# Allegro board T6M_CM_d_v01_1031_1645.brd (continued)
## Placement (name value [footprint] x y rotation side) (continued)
R199  0  [R0402]  58.61 102.4 90 top
R200  8.06K  [R0402]  64.13 81.48 180 bottom
R202  100  [R0402]  82.38 29.39 270 bottom
R203  100  [R0402]  80.35 29.39 90 bottom
R204  0  [R0402]  77.23 28.09 180 bottom
R205  0  [R0402]  111.55 17.69 0 top
R206  0  [R0402]  107.77 29.93 180 bottom
R207  0  [R0402]  101.99 17.6 0 top
R208  0  [R0402]  97.73 29.79 0 bottom
R209  0  [R0402]  68.72 21.5 180 bottom
R210  0  [R0402]  65.23 29.2 180 bottom
R211  0  [R0402]  60.69 28.7 0 bottom
R212  0  [R0402]  50.38 19.02 180 top
R213  12.1K  [R0402]  20.37 7.73 0 top
R214  12.1K  [R0402]  20.37 6.71 180 top
R215  100  [R0402]  24.62 11.61 90 top
R216  2.2  [R0402]  22.6 11.61 270 top
R217  0  [R0402]  46.35 19.45 0 top
R218  100  [R0402]  23.61 11.61 270 top
R219  1K  [R0402]  116.44 66.16 0 bottom
R220  1K  [R0402]  116.44 65.15 180 bottom
R221  0  [R0402]  126.78 65.4 0 top
R222  0  [R0402]  116.44 64.13 0 bottom
R223  1K  [R0402]  128.56 63.42 180 top
R224  0  [R0402]  122.72 67.03 270 bottom
R225  0  [R0402]  126.08 60.24 180 top
R226  1K  [R0402]  116.44 69.27 180 bottom
R227  0  [R0402]  116.44 68.24 0 bottom
R228  150  [R0402]  126.08 62.27 180 top
R229  51  [R0402]  126.08 61.26 0 top
R231  0  [R0402]  147.83 154.82 90 top
R232  0  [R0402]  156.95 141.2 0 top
R233  0  [R0402]  156.97 142.2 0 top
R234  0  [R0402]  146.84 154.82 270 top
R253  100K  [R0402]  81.43 121.04 270 bottom
R254  0  [R0402]  82.72 121.06 270 bottom
R255  0  [R0402]  80.39 121.04 270 top
R256  10K  [R0402]  87.45 129.39 270 bottom
R257  274  [R0402]  69.49 131.03 180 bottom
R258  100K  [R0402]  88.6 129.39 90 bottom
R259  4.7K  [R0402]  54.36 123.47 90 top
R260  240  [R0402]  57.75 133.13 180 bottom
R261  1K  [R0402]  49 133.45 270 bottom
R262  1K  [R0402]  49.68 138.39 180 bottom
R263  0  [R0402]  156.95 137.37 180 top
R264  0  [R0402]  181.68 37.95 0 top
R265  0  [R0402]  181.68 36.94 0 top
R266  0  [R0402]  181.76 41.68 0 top
R267  0  [R0402]  181.76 40.66 0 top
R268  0  [R0402]  181.68 58 0 top
R269  0  [R0402]  181.68 56.98 0 top
R270  0  [R0402]  181.82 61.68 0 top
R271  0  [R0402]  181.82 60.67 0 top
R272  0  [R0402]  83.75 121.06 270 bottom
R273  0  [R0402]  168.07 105.98 270 top
R274  0  [R0402]  169.1 105.98 270 top
R275  5.1K  [R0402]  159.47 144.08 0 top
R276  5.1K  [R0402]  156.95 144.2 0 top
R277  5.1K  [R0402]  156.95 145.22 0 top
R278  5.1K  [R0402]  156.82 150.2 0 top
R279  5.1K  [R0402]  150.95 154.79 90 top
R280  5.1K  [R0402]  139.55 133.18 270 top
R281  5.1K  [R0402]  135.33 137.04 180 top
R283  5.1K  [R0402]  138.58 153.68 90 top
R284  5.1K  [R0402]  160.23 138.49 0 top
R285  5.1K  [R0402]  156.8 149.21 0 top
R286  5.1K  [R0402]  156.95 140.21 0 top
R287  5.1K  [R0402]  149.81 154.79 90 top
R288  5.1K  [R0402]  156.95 138.54 0 top
R289  5.1K  [R0402]  154.94 133.18 0 top
R290  150  [R0402]  70.91 146.42 270 bottom
R291  150  [R0402]  72.03 146.42 270 bottom
R292  150  [R0402]  73.12 146.42 270 bottom
R293  10K  [R0402]  86.94 148.48 270 bottom
R294  8.2K  [R0402]  69.38 126.52 0 bottom
R295  5.1K  [R0402]  137.57 153.68 90 top
R296  5.1K  [R0402]  139.6 153.68 90 top
R297  5.1K  [R0402]  142.51 154.7 180 top
R298  47K  [R0402]  83.74 148.48 90 top
R299  5.1K  [R0402]  145.8 154.84 270 top
R300  47K  [R0402]  81.58 148.48 90 top
R301  5.1K  [R0402]  159.96 150.24 90 top
R302  47K  [R0402]  80.51 148.48 90 top
R303  5.1K  [R0402]  158.95 150.24 90 top
R304  47K  [R0402]  82.67 148.48 90 top
R305  5.1K  [R0402]  154.94 135.19 180 top
R306  5.1K  [R0402]  156.77 147.2 0 top
R307  5.1K  [R0402]  156.8 148.22 0 top
R308  5.1K  [R0402]  156.77 146.21 0 top
R309  5.1K  [R0402]  160.09 141.03 180 top
R310  5.1K  [R0402]  160.07 142.1 180 top
R311  4.7K  [R0402]  63.34 117.87 270 top
R312  22  [R0402]  67.82 121.34 270 top
R313  49.9K  [R0402]  77.34 148.48 90 top
R314  0  [R0603]  71.96 149.69 0 top
R315  2.74K  [R0603]  68.76 148.29 180 top
R316  4.7K  [R0402]  74.54 121.06 270 bottom
R317  4.7K  [R0402]  72.39 118.91 90 top
R318  4.7K  [R0402]  72.39 121.04 270 top
R319  4.7K  [R0402]  73.5 118.91 90 bottom
R320  4.7K  [R0402]  75.86 118.78 90 bottom
R321  4.7K  [R0402]  75.86 121.04 270 bottom
R322  4.7K  [R0402]  73.5 118.91 90 top
R323  4.7K  [R0402]  73.48 121.04 270 top
R324  4.7K  [R0402]  79.32 118.76 90 bottom
R325  4.7K  [R0402]  78.23 121.04 270 bottom
R326  4.7K  [R0402]  75.86 118.78 90 top
R327  4.7K  [R0402]  75.86 121.04 270 top
R328  4.7K  [R0402]  77.75 129.79 90 bottom
R329  4.7K  [R0402]  80.41 118.76 90 bottom
R330  4.7K  [R0402]  80.39 121.04 270 bottom
R331  4.7K  [R0402]  76.93 121.04 270 top
R332  4.7K  [R0402]  71.8 119.05 270 bottom
R333  4.7K  [R0402]  78.23 118.76 90 bottom
R334  4.7K  [R0402]  76.93 118.76 90 bottom
R335  4.7K  [R0402]  79.32 121.04 270 bottom
R336  4.7K  [R0402]  74.54 121.04 270 top
R337  4.7K  [R0402]  76.93 121.04 270 bottom
R338  4.7K  [R0402]  76.93 118.76 90 top
R339  4.7K  [R0402]  81.5 118.76 90 bottom
R340  4.7K  [R0402]  71.29 121.04 270 top
R341  4.7K  [R0402]  71.29 118.91 90 top
R342  4.7K  [R0402]  73.48 121.04 270 bottom
R343  4.7K  [R0402]  70.01 118.96 270 top
R344  4.7K  [R0402]  68.92 118.97 270 top
R345  4.7K  [R0402]  78.23 118.76 90 top
R346  4.7K  [R0402]  78.23 121.04 270 top
R471  0  [R0402]  23.15 3.71 180 top
R472  0  [R0402]  23.15 4.72 180 top
R497  1K  [R0402]  68.1 96.71 90 top
R501  330  [R0402]  150.91 69.66 180 top
R502  4.7K  [R0402]  161.31 57.25 270 top
R503  10K  [R0402]  164.58 60.02 0 top
R504  6.04K  [R0402]  164.61 70.2 180 top
R505  10K  [R0402]  164.61 69.06 0 top
R506  33  [R0402]  151.39 76.49 180 top
R507  33  [R0402]  151.39 75.39 180 top
R508  33  [R0402]  151.47 74.3 180 top
R509  4.7K  [R0402]  149.63 61.72 180 top
R510  4.7K  [R0402]  149.63 62.74 180 top
R511  4.7K  [R0402]  149.63 60.7 180 top
R512  4.7K  [R0402]  149.63 59.69 180 top
R513  0  [R0402]  155.38 72.31 270 top
R514  4.7K  [R0402]  160.29 57.25 270 top
R515  4.7K  [R0402]  159.28 57.25 270 top
R516  4.7K  [R0402]  143.01 60.93 90 top
R517  4.7K  [R0402]  162.33 57.25 270 top
R518  4.7K  [R0402]  163.34 57.25 270 top
R519  33  [R0402]  144.03 60.93 90 top
R520  0  [R0402]  167.48 103.99 270 top
R521  0  [R0402]  135.62 56.83 0 top
R522  33  [R0402]  175.92 93.84 270 top
R523  33  [R0402]  174.91 93.84 270 top
R524  33  [R0402]  176.94 93.84 270 top
R525  10K  [R0402]  171.58 106.37 180 top
R526  1.6K  [R0402]  183.91 93.88 180 top
R527  10K  [R0402]  172.42 97.32 180 top
R528  10K  [R0402]  165.53 87.17 270 top
R529  10K  [R0402]  175.75 88.85 0 top
R530  33  [R0402]  165.47 89.2 270 top
R531  47K  [R0402]  165.57 91.33 270 top
R532  10K  [R0402]  178.13 93.85 90 top
R533  10K  [R0402]  172.04 98.34 180 top
R534  10K  [R0402]  168.48 103.99 270 top
R536  4.7K  [R0402]  59.63 163.9 90 top
R537  1K  [R0402]  60.78 163.9 90 top
R538  4.7K  [R0402]  63.06 163.9 90 top
R539  4.7K  [R0402]  64.21 163.9 90 top
R540  4.7K  [R0402]  61.92 163.9 90 top
R541  4.7K  [R0402]  59.63 166.44 90 top
R542  4.7K  [R0402]  64.26 147.55 0 top
R543  0  [R0402]  64.26 148.56 180 top
R544  10K  [R0402]  57.57 145.83 270 top
R545  22.1  [R0402]  64.26 145.51 180 top
R546  10K  [R0402]  56.55 145.83 270 top
R547  0  [R0402]  70.25 161.93 90 top
R548  10K  [R0402]  54.36 145.8 270 top
R549  0  [R0402]  64.26 146.53 180 top
R550  10K  [R0402]  53.35 145.8 270 top
R551  1K  [R0402]  49.96 145.57 180 bottom
R552  1K  [R0402]  49.96 146.58 180 bottom
R553  10K  [R0402]  69.23 161.93 270 top
R554  10K  [R0402]  49.96 147.58 180 bottom
R555  10K  [R0402]  74.97 151.48 180 top
R556  10K  [R0402]  55.45 145.83 270 top
R557  10K  [R0402]  52.27 145.83 270 top
R558  1.02K  [R0402]  65.59 159 0 top
R559  4.99K  [R0402]  52.16 162.19 90 top
R560  0  [R0402]  64.26 149.58 0 top
R561  0  [R0402]  63.06 166.44 90 top
R562  0  [R0402]  61.92 166.44 90 top
R563  0  [R0402]  64.21 166.44 90 top
R564  4.99K  [R0603]  36.07 149.12 180 top
R565  0  [R1206]  41.59 147.96 90 top
R566  4.7K  [R0402]  165.56 142.89 270 top
R567  4.7K  [R0402]  170 142.94 270 top
R568  1K  [R0402]  167.72 142.94 270 top
R569  4.7K  [R0402]  163.53 142.89 270 top
R570  4.7K  [R0402]  161.5 142.89 270 top
R571  4.7K  [R0402]  168.86 142.94 270 top
R572  4.7K  [R0402]  169.34 161.2 90 top
R573  0  [R0402]  166.58 167.79 180 top
R574  10K  [R0402]  172.09 161.37 90 top
R575  22.1  [R0402]  177.84 165.12 0 top
R576  10K  [R0402]  173.1 161.37 90 top
R577  0  [R0402]  177.84 163.85 0 top
R578  10K  [R0402]  175.29 161.4 90 top
R579  0  [R0402]  166.58 166.52 180 top
R580  10K  [R0402]  176.3 161.4 90 top
R581  1K  [R0402]  181.17 154.8 0 bottom
R582  1K  [R0402]  180.54 156.83 0 top
R583  10K  [R0402]  177.84 166.39 180 top
R584  10K  [R0402]  178.45 161.4 90 top
R585  10K  [R0402]  166.58 165.25 0 top
R586  10K  [R0402]  174.2 161.37 90 top
R587  10K  [R0402]  177.38 161.37 90 top
R588  1.02K  [R0402]  164.7 149.07 180 top
R589  4.99K  [R0402]  177.5 145.83 270 top
R590  0  [R0402]  167.29 161.21 90 top
R591  0  [R0402]  164.54 142.89 270 top
R592  0  [R0402]  166.58 142.89 270 top
R593  0  [R0402]  162.51 142.89 270 top
R594  4.99K  [R0603]  194.46 145.2 270 top
R595  0  [R1206]  194.49 149.21 270 top
R596  1K  [R0402]  65.59 157.98 0 top
R597  1K  [R0402]  164.69 150.14 180 top
R614  10K  [R0402]  147.29 51.44 90 top
R615  10K  [R0402]  145.26 51.44 90 top
R616  10K  [R0402]  140.06 51.75 90 top
R617  10K  [R0402]  135.04 50.04 90 top
R618  0  [R0402]  131.17 39.94 180 top
R619  1K  [R0402]  125.98 46.85 0 top
R620  10K  [R0402]  138.07 40.07 0 bottom
R621  0  [R0402]  136.79 50.08 90 top
R622  0  [R0402]  88.78 164.13 180 bottom
R623  0  [R0402]  135.74 166.52 0 top
R624  1K  [R0402]  134.85 26.57 90 top
R625  0  [R0402]  131.16 41.53 180 top
R626  10K  [R0402]  161.43 45.71 0 top
R627  0  [R0402]  179.66 131.77 90 top
R628  10_4  [R0402]  137.58 32.68 0 bottom
R629  0  [R0805]  157.11 51.67 270 top
R630  0  [R0805]  159.14 51.67 270 top
R631  4.7K  [R0402]  32.45 62.2 90 top
R632  4.7K  [R0402]  38.01 44.1 270 top
R633  4.7K  [R0402]  32.45 64.07 270 top
R634  4.7K  [R0402]  30.25 45.51 270 top
R635  4.7K  [R0402]  27.32 62.09 270 top
R636  0  [R0402]  27.32 63.89 270 top
R637  33  [R0402]  27.28 60.31 90 top
R638  33  [R0402]  28.52 52.33 270 top
R639  33  [R0402]  28.59 46.32 270 top
R640  150  [R0402]  31.42 43.84 180 top
R641  150  [R0402]  30.08 47.99 180 top
R642  150  [R0402]  30.26 56 270 top
R643  0  [R0402]  135.28 161.24 180 top
R644  0  [R0402]  132.65 153.9 270 top
R645  0  [R0402]  132.29 159.5 270 top
R646  0  [R0402]  120.42 162.73 180 top
R647  0  [R0402]  148.48 158.55 0 top
R648  0  [R0402]  140.55 161.24 180 top
R649  4.7K  [R0402]  161.54 32.57 180 top
R650  4.7K  [R0402]  161.54 33.59 180 top
R651  4.7K  [R0402]  24.98 16.26 270 top
R652  4.7K  [R0402]  23.97 16.26 270 top
R653  4.7K  [R0402]  145.3 60.93 270 top
R654  1K  [R0402]  23.92 29.78 90 top
R655  10K  [R0402]  110.19 162.23 270 top
R656  1K  [R0402]  173.23 33.59 0 top
R657  10K  [R0402]  120.42 153.55 0 top
R658  0  [R0402]  36.86 57.36 180 top
R659  33  [R0402]  30.26 54.25 90 top
R660  0  [R0402]  180.69 131.72 90 top
R661  0  [R0402]  181.85 131.72 90 top
R662  0  [R0402]  81.79 166.75 180 top
R663  2.7K  [R0402]  123.9 172.63 180 top
R664  2.7K  [R0402]  123.9 171.61 180 top
R665  10K  [R0402]  137.05 161.19 0 top
R666  4.7K  [R0402]  123.9 170.59 180 top
R667  10K  [R0402]  123.9 169.58 180 top
R668  4.7K  [R0402]  131.27 160.4 90 top
R669  10K  [R0402]  140.55 162.25 0 top
R670  33  [R0402]  68.23 144.81 0 bottom
R671  4.7K  [R0402]  148.48 157.54 0 top
R672  10K  [R0402]  135.74 169.57 0 top
R673  4.7K  [R0402]  123.9 166.52 0 top
R674  10K  [R0402]  135.74 170.59 0 top
R675  33  [R0402]  68.23 145.85 0 bottom
R676  0  [R0402]  81.79 165.66 180 top
R677  10K  [R0402]  123.9 165.51 180 top
R678  0  [R0402]  81.79 164.62 180 top
R679  0  [R0402]  138.68 165.26 180 top
R680  10K  [R0402]  135.74 164.49 180 top
R681  0  [R0402]  124.1 164.31 0 top
R682  100  [R0402]  135.74 171.6 0 top
R683  0  [R0402]  124.1 163.28 0 top
R684  0  [R0402]  138.68 164.23 180 top
R685  4.7K  [R0402]  90.86 169.46 180 bottom
R686  4.7K  [R0402]  73.73 178.6 0 bottom
R687  100  [R0402]  102.85 169.96 180 bottom
R688  100  [R0402]  60.39 178.29 0 bottom
R689  10K  [R0402]  90.86 170.47 0 bottom
R690  10K  [R0402]  90.86 171.49 0 bottom
R691  10K  [R0402]  90.86 172.51 0 bottom
R692  10K  [R0402]  90.86 173.52 0 bottom
R693  10K  [R0402]  90.86 174.54 0 bottom
R694  10K  [R0402]  90.86 175.55 0 bottom
R695  10K  [R0402]  90.86 176.57 0 bottom
R696  10K  [R0402]  90.86 177.59 0 bottom
R697  10K  [R0402]  102.85 178.09 180 bottom
R698  10K  [R0402]  102.85 177.07 180 bottom
R699  10K  [R0402]  102.85 176.05 180 bottom
R700  10K  [R0402]  102.85 175.04 180 bottom
R701  4.7K  [R0402]  106.48 172.12 180 bottom
R702  4.7K  [R0402]  122.48 172.51 180 bottom
R703  10K  [R0402]  102.85 174.02 180 bottom
R704  4.7K  [R0402]  118.82 174.16 0 bottom
R705  10K  [R0402]  102.85 173.01 180 bottom
R706  4.7K  [R0402]  135.74 173.39 0 bottom
R707  10K  [R0402]  102.85 171.99 180 bottom
R708  4.7K  [R0402]  106.48 174.16 180 bottom
R709  10K  [R0402]  102.85 170.97 180 bottom
R710  10K  [R0402]  122.48 174.54 0 bottom
R711  10K  [R0402]  122.48 175.55 0 bottom
R712  10K  [R0402]  122.48 176.57 0 bottom
R713  10K  [R0402]  122.48 177.59 0 bottom
R714  10K  [R0402]  122.48 178.6 0 bottom
R715  10K  [R0402]  122.48 179.62 0 bottom
R716  10K  [R0402]  122.48 180.63 0 bottom
R717  10K  [R0402]  122.48 181.65 0 bottom
R718  100  [R0402]  122.48 173.52 0 bottom
R719  100  [R0402]  106.48 173.14 0 bottom
R720  10K  [R0402]  137.77 182.52 180 top
R721  10K  [R0402]  137.77 181.5 180 top
R722  10K  [R0402]  137.77 180.49 180 top
R723  10K  [R0402]  137.77 179.47 180 top
R724  10K  [R0402]  135.74 177.46 180 bottom
R725  10K  [R0402]  135.74 176.44 180 bottom
R726  10K  [R0402]  135.74 175.43 180 bottom
R727  10K  [R0402]  135.74 174.41 180 bottom
R728  10K  [R0402]  154.1 170.98 0 bottom
R729  10K  [R0402]  154.1 172 0 bottom
R730  10K  [R0402]  154.1 173.01 0 bottom
R731  10K  [R0402]  154.1 174.03 0 bottom
R732  10K  [R0402]  154.1 175.05 0 bottom
R733  10K  [R0402]  154.1 176.06 0 bottom
R734  4.7K  [R0402]  154.1 168.95 180 bottom
R735  4.7K  [R0402]  118.46 176.97 180 top
R736  10K  [R0402]  154.1 177.08 0 bottom
R737  4.7K  [R0402]  106.48 179.39 0 top
R738  4.7K  [R0402]  106.48 176.34 0 top
R739  4.7K  [R0402]  106.48 175.32 0 top
R740  10K  [R0402]  154.1 178.09 0 bottom
R741  10K  [R0402]  161.42 178.78 270 bottom
R742  10K  [R0402]  160.28 178.78 270 bottom
R743  4.7K  [R0402]  154.1 169.97 180 bottom
R744  10K  [R0402]  159.14 178.78 270 bottom
R745  10K  [R0402]  166.09 176.57 180 bottom
R746  10K  [R0402]  166.09 175.55 180 bottom
R747  10K  [R0402]  166.09 174.54 180 bottom
R748  10K  [R0402]  166.09 173.52 180 bottom
R749  10K  [R0402]  166.09 172.51 180 bottom
R750  100  [R0402]  166.09 171.49 180 bottom
R751  100  [R0402]  118.46 177.97 180 top
R752  100  [R0402]  106.48 178.37 0 top
R753  100  [R0402]  106.48 177.35 0 top
R754  100  [R0402]  106.48 174.31 0 top
R755  0  [R0402]  110.05 181.67 180 bottom
R756  100  [R0402]  106.48 170.22 0 top
R757  100  [R0402]  106.48 169.2 0 top
R758  100  [R0402]  106.48 171.25 0 top
R759  4.7K  [R0402]  120.71 164.11 0 top
R760  4.7K  [R0402]  118.2 173 180 top
R761  100  [R0402]  118.2 169.93 180 top
R762  10K  [R0402]  118.2 171.99 0 top
R763  10K  [R0402]  118.2 170.97 180 top
R764  0  [R0402]  106.48 173.29 0 top
R765  0  [R0402]  118.15 174.68 270 top
R766  4.7K  [R0402]  109.53 167.55 270 bottom
R767  4.7K  [R0402]  118.2 166.85 180 top
R768  100  [R0402]  106.48 165.14 0 top
R769  10K  [R0402]  118.22 163.77 0 top
R770  100  [R0402]  106.48 164.12 0 top
R771  10K  [R0402]  118.2 165.79 0 top
R772  10K  [R0402]  118.2 164.77 180 top
R773  0  [R0402]  127.15 164.89 90 bottom
R774  0  [R0402]  126.12 164.89 90 bottom
R775  0  [R0402]  142.93 161.15 180 top
R776  10K  [R0402]  142.6 30.61 0 bottom
R777  10K  [R0402]  150.34 51.44 90 top
R778  10K  [R0402]  112.73 171.76 180 bottom
R779  4.7K  [R0402]  90.86 168.44 0 bottom
R780  4.7K  [R0402]  102.85 163.87 180 bottom
R781  4.7K  [R0402]  102.85 162.85 180 bottom
R782  4.7K  [R0402]  90.86 165.39 0 bottom
R783  100  [R0402]  90.86 164.38 180 bottom
R784  4.7K  [R0402]  102.85 167.93 180 bottom
R785  4.7K  [R0402]  102.85 166.91 180 bottom
R786  4.7K  [R0402]  102.85 165.89 180 bottom
R787  4.7K  [R0402]  102.85 164.88 180 bottom
R788  33  [R0402]  27.84 48.05 0 top
R789  33  [R0402]  30 43.59 90 top
R790  4.7K  [R0402]  90.86 167.43 0 bottom
R791  4.7K  [R0402]  90.86 166.41 0 bottom
R792  100  [R0402]  135.74 165.51 0 top
R793  4.7K  [R0402]  88.78 163.12 0 bottom
R794  100K  [R0402]  160.1 175.28 180 top
R795  75  [R0402]  127.04 163.24 0 bottom
R796  510  [R0402]  132.67 175.43 90 top
R797  510  [R0402]  131.52 175.43 90 top
R798  510  [R0402]  130.38 175.43 90 top
R799  10K  [R0402]  114.59 171.75 180 bottom
R800  10K  [R0402]  105.37 159.83 90 top
R801  100K  [R0402]  102.26 163.62 0 top
R802  10K  [R0402]  124.2 153.69 0 top
R803  100K  [R0402]  118.79 177.57 90 bottom
R804  0  [R0805]  154.21 56.52 180 top
R805  510  [R0402]  129.24 175.43 90 top
R806  100K  [R0402]  160.1 176.3 180 top
R807  100K  [R0402]  155.56 181.51 270 top
R808  100  [R0402]  32.19 10.54 270 top
R809  100K  [R0402]  102.85 177.58 180 top
R810  100K  [R0402]  102.85 178.59 180 top
R811  100K  [R0402]  102.85 180.63 180 top
R812  4.7K  [R0402]  104.72 182.49 90 bottom
R813  100  [R0402]  191.66 11.54 270 top
R814  10K  [R0402]  156.94 40.74 0 bottom
R815  0  [R0402]  131.57 39.54 270 top
R816  1.2K  [R0402]  156.94 39.73 180 bottom
R817  100  [R0402]  192.8 11.54 90 top
R818  33  [R0402]  65.99 185.21 270 top
R819  33  [R0402]  171.66 185.21 270 top
R820  33  [R0402]  67.14 185.21 270 top
R821  33  [R0402]  170.51 185.21 270 top
R822  33  [R0402]  95.71 185.21 270 top
R823  33  [R0402]  169.37 185.21 270 top
R824  33  [R0402]  96.85 185.21 270 top
R825  33  [R0402]  168.23 185.21 270 top
R826  33  [R0402]  168.23 184.95 270 bottom
R827  33  [R0402]  173.69 187.87 270 bottom
R828  33  [R0402]  169.37 184.95 270 bottom
R829  33  [R0402]  172.67 187.87 270 bottom
R830  33  [R0402]  171.66 187.87 270 bottom
R831  33  [R0402]  64.85 185.21 90 top
R832  100  [R0402]  64.85 185.21 90 bottom
R833  33  [R0402]  63.71 185.21 90 top
R834  100  [R0402]  63.71 185.21 90 bottom
R835  33  [R0402]  57.67 184.92 90 bottom
R836  33  [R0402]  62.56 185.21 90 top
R837  100  [R0402]  62.56 185.21 90 bottom
R838  33  [R0402]  119.46 188.13 90 bottom
R839  33  [R0402]  61.42 185.21 90 top
R840  100  [R0402]  61.42 185.21 90 bottom
R841  33  [R0402]  179.84 188.2 270 top
R842  33  [R0402]  60.28 185.21 90 top
R843  100  [R0402]  60.28 185.21 90 bottom
R844  33  [R0402]  178.32 188.2 270 top
R845  100K  [R0402]  64.85 188.13 90 top
R846  33  [R0402]  59.13 185.21 90 top
R847  100  [R0402]  59.13 185.21 90 bottom
R848  100K  [R0402]  63.71 188.13 90 top
R849  100K  [R0402]  62.56 188.13 90 top
R850  100K  [R0402]  61.42 188.13 90 top
R851  100K  [R0402]  60.28 188.13 90 top
R852  100K  [R0402]  59.13 188.13 90 top
R853  100K  [R0402]  64.85 188.13 90 bottom
R854  100K  [R0402]  63.71 188.13 90 bottom
R855  100K  [R0402]  62.56 188.13 90 bottom
R856  100K  [R0402]  61.42 188.13 90 bottom
R857  100K  [R0402]  60.28 188.13 90 bottom
R858  100K  [R0402]  59.13 188.13 90 bottom
R859  33  [R0402]  78.57 185.21 270 bottom
R860  33  [R0402]  135.97 185.21 270 top
R861  33  [R0402]  151.97 184.95 270 bottom
R862  33  [R0402]  77.42 185.21 270 bottom
R863  33  [R0402]  134.83 185.21 270 top
R864  33  [R0402]  150.83 184.95 270 bottom
R865  33  [R0402]  76.28 185.21 270 bottom
R866  33  [R0402]  133.81 185.21 270 top
R867  33  [R0402]  149.69 184.95 270 bottom
R868  33  [R0402]  75.14 185.21 270 bottom
R869  33  [R0402]  132.66 185.21 270 top
R870  33  [R0402]  148.54 184.95 270 bottom
R871  33  [R0402]  80.85 185.21 270 top
R872  33  [R0402]  131.52 185.21 270 bottom
R873  33  [R0402]  153.11 185.21 270 top
R874  33  [R0402]  79.71 185.21 270 top
R875  33  [R0402]  130.51 185.21 270 bottom
R876  33  [R0402]  151.97 185.21 270 top
R877  33  [R0402]  78.57 185.21 270 top
R878  33  [R0402]  129.49 185.21 270 bottom
R879  33  [R0402]  150.83 185.21 270 top
R880  33  [R0402]  77.42 185.21 270 top
R881  33  [R0402]  128.48 185.21 270 bottom
R882  33  [R0402]  149.69 185.21 270 top
R883  33  [R0402]  91.64 185.6 270 bottom
R884  33  [R0402]  123.78 185.21 270 top
R885  33  [R0402]  167.08 184.95 270 bottom
R886  33  [R0402]  90.65 185.26 270 bottom
R887  33  [R0402]  122.63 185.21 270 top
R888  33  [R0402]  165.94 184.95 270 bottom
R889  33  [R0402]  89.67 185.26 270 bottom
R890  33  [R0402]  121.49 185.21 270 top
R891  33  [R0402]  164.8 184.95 270 bottom
R892  33  [R0402]  88.6 184.85 270 bottom
R893  33  [R0402]  120.35 185.21 270 top
R894  33  [R0402]  163.66 184.95 270 bottom
R895  33  [R0402]  94.57 185.21 270 top
R896  33  [R0402]  118.32 185.21 270 bottom
R897  33  [R0402]  167.08 185.21 270 top
R898  33  [R0402]  93.42 185.21 270 top
R899  33  [R0402]  117.17 185.21 270 bottom
R900  33  [R0402]  165.94 185.21 270 top
R901  33  [R0402]  92.28 185.21 270 top
R902  33  [R0402]  106.27 183.8 180 top
R903  33  [R0402]  164.8 185.21 270 top
R904  33  [R0402]  91.14 185.21 270 top
R905  33  [R0402]  106.24 186.81 0 top
R906  33  [R0402]  171.66 184.95 270 bottom
R907  33  [R0402]  67.14 188.13 270 bottom
R908  33  [R0402]  87.07 188.13 270 bottom
R909  33  [R0402]  103.13 188.86 180 bottom
R910  33  [R0402]  65.99 185.21 270 bottom
R911  33  [R0402]  86.31 165.31 270 bottom
R912  33  [R0402]  102.85 161.83 180 bottom
R913  33  [R0402]  73.99 188.13 270 bottom
R914  33  [R0402]  85.04 188.13 270 bottom
R915  33  [R0402]  106.24 186.81 0 bottom
R916  33  [R0402]  72.85 185.21 270 bottom
R917  33  [R0402]  87.33 165.3 90 bottom
R918  33  [R0402]  102.85 168.43 180 top
R919  33  [R0402]  71.71 188.13 270 bottom
R920  33  [R0402]  83.01 188.13 270 bottom
R921  33  [R0402]  103.13 186.83 0 bottom
R922  33  [R0402]  70.56 185.21 270 bottom
R923  33  [R0402]  81.99 185.21 270 bottom
R924  33  [R0402]  103.13 184.79 0 bottom
R925  33  [R0402]  69.42 188.13 270 bottom
R926  33  [R0402]  80.85 188.13 270 bottom
R927  33  [R0402]  106.24 185.79 0 bottom
R928  33  [R0402]  68.28 185.21 270 bottom
R929  33  [R0402]  79.71 185.21 270 bottom
R930  33  [R0402]  103.13 183.78 0 bottom
R931  33  [R0402]  76.28 188.13 270 top
R932  33  [R0402]  90 188.13 270 top
R933  33  [R0402]  119.33 188.13 270 top
R934  33  [R0402]  75.14 185.21 270 top
R935  33  [R0402]  94.22 162.06 90 top
R936  33  [R0402]  102.84 171.48 180 top
R937  33  [R0402]  73.99 188.13 270 top
R938  33  [R0402]  87.71 188.13 270 top
R939  33  [R0402]  106.24 188.84 0 top
R940  33  [R0402]  72.85 185.21 270 top
R941  33  [R0402]  86.57 185.21 270 top
R942  33  [R0402]  102.84 172.5 180 top
R943  33  [R0402]  71.71 188.13 270 top
R944  33  [R0402]  85.42 188.13 270 top
R945  33  [R0402]  101.17 188.13 270 top
R946  33  [R0402]  70.56 185.21 270 top
R947  33  [R0402]  84.28 185.21 270 top
R948  33  [R0402]  100.28 185.21 270 top
R949  33  [R0402]  69.42 188.13 270 top
R950  33  [R0402]  83.14 188.13 270 top
R951  33  [R0402]  99.14 188.13 270 top
R952  33  [R0402]  68.28 185.21 270 top
R953  33  [R0402]  81.99 185.21 270 top
R954  33  [R0402]  98 185.21 270 top
R955  33  [R0402]  128.48 188.13 270 bottom
R956  33  [R0402]  147.4 187.87 270 bottom
R957  33  [R0402]  162.51 187.87 270 bottom
R958  33  [R0402]  126.32 185.21 270 bottom
R959  33  [R0402]  146.26 184.95 270 bottom
R960  33  [R0402]  161.37 184.95 270 bottom
R961  33  [R0402]  126.19 188.13 270 bottom
R962  33  [R0402]  145.11 187.87 270 bottom
R963  33  [R0402]  158.83 188 270 bottom
R964  33  [R0402]  124.03 185.21 270 bottom
R965  33  [R0402]  143.97 184.95 270 bottom
R966  33  [R0402]  157.69 184.95 270 bottom
R967  33  [R0402]  123.9 188.13 270 bottom
R968  33  [R0402]  142.83 187.87 270 bottom
R969  33  [R0402]  156.54 188 270 bottom
R970  33  [R0402]  122.74 182.66 0 bottom
R971  33  [R0402]  141.49 185.18 270 top
R972  33  [R0402]  155.4 184.95 270 bottom
R973  33  [R0402]  121.62 188.13 270 bottom
R974  33  [R0402]  138.26 185.21 270 top
R975  33  [R0402]  154.26 188 270 bottom
R976  33  [R0402]  141.93 172.47 180 bottom
R977  33  [R0402]  150.07 165.17 0 bottom
R978  33  [R0402]  153.11 184.95 270 bottom
R979  33  [R0402]  133.68 188.13 270 top
R980  33  [R0402]  147.78 188.13 270 top
R981  33  [R0402]  163.66 188.13 270 top
R982  33  [R0402]  141.5 171.36 180 bottom
R983  33  [R0402]  146.26 185.21 270 top
R984  33  [R0402]  162.51 185.21 270 top
R985  33  [R0402]  130.51 188.13 270 top
R986  33  [R0402]  145.49 188.13 270 top
R987  33  [R0402]  161.37 188.13 270 top
R988  33  [R0402]  141.94 170.3 180 bottom
R989  33  [R0402]  151.75 163.36 0 bottom
R990  33  [R0402]  160.23 185.21 270 top
R991  33  [R0402]  128.22 188.13 270 top
R992  33  [R0402]  143.34 188.13 270 top
R993  33  [R0402]  157.69 188.13 270 top
R994  33  [R0402]  141.61 169.26 180 bottom
R995  33  [R0402]  153.13 163.5 270 bottom
R996  33  [R0402]  156.54 185.21 270 top
R997  33  [R0402]  125.94 188.13 270 top
R998  33  [R0402]  141.1 188.13 270 top
R999  33  [R0402]  155.4 188.13 270 top
R1000  33  [R0402]  141.95 166.37 180 bottom
R1001  33  [R0402]  154.5 163.35 0 bottom
R1002  33  [R0402]  154.26 185.21 270 top
R1003  10K  [R0402]  116.11 162.78 0 top
R1004  10K  [R0402]  122.01 149.25 0 top
R1005  10K  [R0402]  162.11 39.97 90 top
R1006  10K  [R0402]  56.92 176.29 180 top
R1007  10K  [R0402]  55.84 186.52 90 top
R1008  10K  [R0402]  161.09 39.97 90 top
R1009  10K  [R0402]  161.44 43.66 0 top
R1010  10K  [R0402]  161.44 44.68 0 top
R1011  10K  [R0402]  162.09 41.88 270 top
R1012  22.1K  [R0402]  59.25 176.25 0 top
R1013  10K  [R0402]  161.07 41.88 270 top
R1014  8.2K  [R0402]  77.42 176.26 180 top
R1015  10K  [R0402]  155.14 54.53 180 top
R1016  10K  [R0402]  155.14 53.51 180 top
R1017  10K  [R0402]  153.74 51.48 90 top
R1018  10K  [R0402]  154.76 51.48 90 top
R1019  0  [R2010]  53.27 185.34 270 top
R1020  10K  [R0402]  151.71 51.48 90 top
R1021  10  [R0402]  45.97 175.46 90 top
R1022  16.5K  [R0402]  45.25 184.21 0 top
R1023  4.7K  [R0402]  47.02 173.42 90 top
R1024  10K  [R0402]  152.73 51.48 90 top
R1025  0  [R0603]  44.34 187.47 0 top
R1026  12.4K  [R0402]  203.4 115.71 180 top
R1027  100  [R0402]  197.85 115.37 90 top
R1028  5.11K  [R0402]  203.4 114.56 180 top
R1029  100K  [R0402]  197.85 113.55 90 top
R1030  0  [R0402]  178.77 119.4 0 top
R1031  4.7K  [R0402]  178.74 123.77 180 top
R1032  330  [R0402]  173.8 131.25 0 top
R1033  1K  [R0402]  199.59 123.86 0 top
R1034  10K  [R0402]  199.62 122.84 0 top
R1035  10K  [R0402]  199.62 121.66 0 top
R1036  10K  [R0402]  186.44 130.64 90 top
R1037  0  [R0402]  187.59 130.64 90 top
R1038  10K  [R0402]  130.12 147.75 180 top
R1039  10K  [R0402]  132.53 151.27 90 top
R1040  1K  [R0402]  74.17 67.22 270 bottom
R1041  1K  [R0402]  191.4 130.36 180 top
R1042  1K  [R0402]  178.75 122.66 180 top
R1043  1K  [R0402]  191.03 135.99 0 top
R1044  1K  [R0402]  70.13 67.09 270 bottom
R1045  1K  [R0402]  178.75 121.57 180 top
R1046  1K  [R0402]  193.49 130.41 0 top
R1047  1K  [R0402]  194.45 135.9 0 top
R1048  510  [R0402]  127.97 175.43 90 top
R1049  1K  [R0402]  96.45 78.57 90 top
R1050  1K  [R0402]  178.77 124.88 180 top
R1051  10K  [R0402]  88.93 101.2 0 top
R1052  33  [R0402]  91.59 96.66 90 top
R1053  4.7K  [R0402]  183.18 136.34 180 top
R1054  200  [R0402]  183.18 138.37 0 top
R1055  33  [R0402]  150.06 160.24 270 top
R1056  10K  [R0402]  153.83 37.92 180 bottom
R1057  10K  [R0402]  154.99 159.79 270 top
R1058  510  [R0402]  126.83 175.43 90 top
R1059  10K  [R0402]  131.01 155.75 180 top
R1060  100K  [R0402]  113.89 181.93 180 bottom
R1061  0  [R0402]  176.05 168.15 90 bottom
R1062  4.7K  [R0402]  164.79 136.17 0 top
R1063  200  [R0402]  164.79 137.19 0 top
R1064  0  [R0402]  177.22 168.15 90 bottom
R1065  10K  [R0402]  150 40.49 0 bottom
R1066  0  [R0402]  183.18 139.38 0 top
R1067  0  [R0402]  164.79 138.2 0 top
R1068  0  [R0402]  14.73 155.48 180 top
R1069  0  [R0402]  142.22 159.6 90 bottom
R1070  4.7K  [R0402]  53.89 169.66 90 top
R1071  0  [R2010]  23.28 97.35 90 top
R1072  100  [R0402]  197.3 188.42 270 top
R1073  100  [R0402]  196.77 173.41 180 top
R1074  1K  [R0402]  84.19 182.19 180 top
R1075  10K  [R0402]  88.84 182.17 0 top
R1076  10K  [R0402]  87.8 183.15 0 top
R1077  10K  [R0402]  156.94 37.69 180 bottom
R1078  10K  [R0402]  156.94 36.68 180 bottom
R1079  0  [R0402]  143.34 40.62 0 bottom
R1080  0  [R0402]  150 41.51 0 bottom
R1081  0  [R0402]  143.34 39.06 0 bottom
R1082  390K  [R0402]  91.7 151.7 0 top
R1083  100K  [R0402]  93.09 151.3 90 top
R1084  4.7K  [R0402]  103.84 137.58 90 top
R1085  2.94K  [R0402]  107.15 139.09 180 top
R1086  9.31K  [R0402]  106.28 138.04 180 top
R1087  4.7K  [R0402]  45.21 107.27 180 top
R1088  2.94K  [R0402]  48.38 104.5 180 top
R1089  3.3K  [R0402]  47.01 104.25 90 top
R1090  10K  [R0402]  78.92 99.28 0 top
R1091  4.02K  [R0402]  82.19 101.4 180 top
R1092  4.02K  [R0402]  82.19 100.25 180 top
R1093  1K  [R0402]  74.06 98.54 180 top
R1094  4.7K  [R0402]  39.97 130.59 90 top
R1095  9.31K  [R0402]  42.59 131.83 180 top
R1096  4.7K  [R0402]  97.55 137.01 90 top
R1097  576  [R0402]  96.38 137.03 270 top
R1098  1K  [R0402]  93.82 136.56 90 bottom
R1099  10K  [R0402]  92.53 103.8 90 top
R1100  4.02K  [R0402]  94.37 108.1 180 top
R1101  4.02K  [R0402]  96.18 108.8 270 top
R1102  1K  [R0402]  92.95 96.67 180 top
R1103  1K  [R0402]  59.45 105.38 0 top
R1104  1K  [R0402]  105.56 131.56 90 top
R1105  1K  [R0402]  177.98 72.84 90 top
R1106  1K  [R0402]  39.42 103.22 180 top
R1107  330K  [R0402]  74.6 160.32 270 top
R1108  4.02K  [R0402]  71.36 164.53 270 top
R1109  4.02K  [R0402]  73.42 164.51 270 top
R1110  1K  [R0402]  74.59 164.29 90 top
R1111  10K  [R0402]  77.29 112.67 180 top
R1112  4.02K  [R0402]  77.77 107.32 90 top
R1113  4.02K  [R0402]  76.75 107.32 90 top
R1114  1K  [R0402]  82.22 114.3 90 top
R1115  10K  [R0402]  50.42 118.11 90 top
R1116  4.02K  [R0402]  45.38 118.55 0 top
R1117  4.02K  [R0402]  45.38 119.57 0 top
R1118  1K  [R0402]  50.41 112.65 270 top
R1119  0  [R0402]  147.19 42.5 0 bottom
R1120  0  [R0402]  196.65 130.6 270 top
R1121  10K  [R0402]  195.52 130.6 270 top
R1122  1K  [R0402]  183.18 135.25 0 top
R1123  4.7K  [R0402]  50.28 6.55 270 top
R1124  10K  [R0402]  128.93 26.09 180 top
R1125  10K  [R0402]  130.41 24.06 180 top
R1126  4.7K  [R0402]  127.9 18.99 0 top
R1127  2K  [R0402]  111.21 162.23 90 top
R1128  2K  [R0402]  122.2 153.55 0 top
R1129  0  [R0805]  117.11 160.49 0 top
R1130  0  [R0805]  119.96 151.02 270 top
R1131  1K  [R0402]  188.3 132.62 270 top
R1132  1K  [R0402]  149.7 46.95 270 bottom
R1133  10K  [R0402]  148.67 46.95 270 bottom
R1134  1K  [R0402]  147.14 55.32 90 top
R1135  10K  [R0402]  148.16 55.32 90 top
R1136  1K  [R0402]  146.47 46.96 270 bottom
R1137  10K  [R0402]  147.61 46.95 270 bottom
R1138  10K  [R0402]  138.07 41.21 0 bottom
R1139  10K  [R0402]  152.1 25.81 270 top
R1140  10K  [R0402]  139.28 26.57 270 top
R1141  10K  [R0402]  141.31 26.57 270 top
R1142  10K  [R0402]  140.29 26.57 270 top
R1143  10K  [R0402]  138.26 26.57 270 top
R1144  10K  [R0402]  142.32 26.57 270 top
R1145  10K  [R0402]  143.34 26.57 270 top
R1146  10K  [R0402]  144.36 26.57 270 top
R1147  10K  [R0402]  145.37 26.57 270 top
R1148  10K  [R0402]  146.39 26.57 270 top
R1149  10K  [R0402]  147.4 26.57 270 top
R1150  10K  [R0402]  137.24 26.57 270 top
R1151  100  [R0402]  36.41 94.66 90 top
R1152  100  [R0402]  40.53 99.57 0 top
R1153  100  [R0402]  31.97 97.97 180 top
R1154  100  [R0402]  31.98 100.04 180 top
R1155  1K  [R0402]  149.32 51.44 270 top
R1156  2K  [R0402]  150.01 53.75 180 top
R1157  1K  [R0402]  148.34 51.45 270 top
R1158  2K  [R0402]  161.98 165.96 180 top
R1159  1K  [R0402]  146.27 51.44 270 top
R1160  2K  [R0402]  147.05 181.55 270 top
R1161  1K  [R0402]  141.14 50.88 270 top
R1162  2K  [R0402]  138.45 58.63 0 top
R1163  1K  [R0402]  144.24 51.44 270 top
R1164  1K  [R0402]  143.26 51.45 270 top
R1165  2K  [R0402]  88.14 179.99 90 bottom
R1166  2K  [R0402]  89.13 179.99 90 bottom
R1167  0  [R0402]  168.03 178.69 270 top
R1168  2K  [R0402]  167.02 178.69 270 top
R1169  0  [R0402]  177.04 182.04 180 top
R1170  0  [R0402]  177.04 184.07 180 top
R1171  2K  [R0402]  177.04 185.08 180 top
R1172  2K  [R0402]  177.04 183.05 180 top
R1173  0  [R0402]  177.04 183.05 180 bottom
R1174  2K  [R0402]  177.04 182.04 0 bottom
R1175  0  [R0402]  170.52 182 270 bottom
R1176  0  [R0402]  171.53 182 270 bottom
R1177  2K  [R0402]  100.32 180.79 270 top
R1178  2K  [R0402]  102.85 176.56 180 top
R1179  1K  [R0402]  150 38.46 0 bottom
R1180  1.5K  [R0402]  147.23 38.39 0 bottom
R1181  1K  [R0402]  147.23 36.36 180 bottom
R1182  1.5K  [R0402]  150 36.43 180 bottom
R1183  1K  [R0402]  147.23 35.34 180 bottom
R1184  1.5K  [R0402]  150 35.41 180 bottom
R1185  1K  [R0402]  147.23 34.33 180 bottom
R1186  1.5K  [R0402]  150 34.4 180 bottom
R1187  0  [R0402]  150 37.44 0 bottom
R1188  2K  [R0402]  147.23 37.38 0 bottom
R1189  0  [R0402]  152.54 41.29 0 bottom
R1190  0  [R0402]  150 39.48 0 bottom
R1191  2K  [R0402]  147.23 39.41 0 bottom
R1192  2K  [R0402]  147.23 41.44 0 bottom
R1193  10K  [R0402]  156.94 35.66 180 bottom
R1194  10K  [R0402]  156.94 34.65 180 bottom
R1195  10K  [R0402]  156.94 38.71 180 bottom
R1196  4.7K  [R0402]  105.74 182.49 90 bottom
R1197  0  [R0402]  179.66 12.49 90 top
R1198  0  [R0402]  174.58 12.47 90 top
R1199  0  [R0402]  182.21 12.47 90 top
R1200  0  [R0402]  183.72 12.47 90 top
R1201  10K  [R0402]  133.75 35.4 0 bottom
R1202  10K  [R0402]  133.75 36.41 0 bottom
R1203  10K  [R0402]  133.75 37.43 0 bottom
R1204  1.2K  [R0402]  133.75 38.45 0 bottom
R1205  0  [R0402]  140.73 36.12 180 bottom
R1206  2K  [R0402]  142.56 36.12 180 bottom
R1207  0  [R0402]  140.73 38.27 180 bottom
R1208  0  [R0402]  140.73 34.97 180 bottom
R1209  2K  [R0402]  142.55 34.97 180 bottom
R1210  2K  [R0402]  140.73 37.26 0 bottom
R1211  4.7K  [R0402]  132.63 166.81 180 bottom
R1212  1K  [R0402]  184.73 12.47 90 top
R1213  10K  [R0402]  178.64 12.49 90 top
R1214  10K  [R0402]  175.6 12.47 90 top
R1215  1K  [R0402]  104.75 83.32 270 top
R1216  1K  [R0402]  90.27 83.92 180 bottom
R1217  10K  [R0402]  136.42 57.9 180 top
R1218  4.7K  [R0402]  173.52 72.4 0 top
R1219  4.7K  [R0402]  170.51 188.13 90 top
R1220  4.7K  [R0402]  169.37 188.13 90 top
R1221  4.7K  [R0402]  168.23 188.13 90 top
R1222  4.7K  [R0402]  173.86 188.08 90 top
R1223  4.7K  [R0402]  172.85 188.08 90 top
R1224  4.7K  [R0402]  170.51 187.87 90 bottom
R1225  4.7K  [R0402]  132.4 165.41 90 bottom
R1226  100  [R0402]  151.02 156.74 180 top
R1227  100  [R0402]  160.97 150.26 90 top
R1228  100  [R0402]  154.94 134.19 180 top
R1229  100  [R0402]  160.23 137.32 180 top
R1230  1K  [R0402]  89.68 129.39 90 bottom
R1231  1K  [R0402]  84.86 100.89 270 top
R1232  1K  [R0402]  112.66 159.57 180 top
R1233  1K  [R0402]  39.47 123.26 270 top
R1234  1K  [R0402]  98.49 145.07 90 top
R1235  1K  [R0402]  94.37 107.1 0 top
R1236  1K  [R0402]  72.35 164.53 90 top
R1237  1K  [R0402]  82.41 1.69 180 top
R1238  1K  [R0402]  79.78 106.3 270 top
R1239  1K  [R0402]  35.26 128.94 270 top
R1240  1K  [R0402]  45.38 116.52 180 top
R1241  1K  [R0402]  50.73 3.09 180 top
R1242  1K  [R0402]  127.86 17.58 0 top
R1243  10K  [R0402]  126.75 166.98 180 bottom
R1244  10K  [R0402]  132.67 168.56 0 bottom
R1245  10K  [R0402]  128.6 166.02 270 bottom
R1246  0  [R0402]  198.24 116.96 180 top
R1247  0  [R0402]  198.28 118.71 180 top
R1248  4.7K  [R0402]  135.71 162.46 0 top
R1249  0  [R0805]  128.9 149.24 180 top
R1250  2K  [R0402]  133.55 151.27 270 top
R1251  100K  [R0402]  43.15 169.07 0 top
R1252  4.7K  [R0402]  102.85 179.61 0 top
R1253  150  [R0402]  96.49 129 270 top
R1254  150  [R0402]  97.63 129 270 top
R1255  150  [R0402]  98.78 129 270 top
R1256  150  [R0402]  99.92 129 270 top
R1257  150  [R0402]  103.02 113.77 90 top
R1258  150  [R0402]  107.66 118.64 180 top
R1259  150  [R0402]  101.06 129 270 top
R1260  150  [R0402]  95.28 129.05 270 top
R1261  4.7K  [R0402]  161.84 174.11 90 top
R1262  10K  [R0402]  17.86 152.75 270 top
R1263  10K  [R0402]  140.59 51.26 0 bottom
R1264  10K  [R0402]  150.72 46.95 270 bottom
R1265  0  [R0402]  203.42 121.67 0 top
R1266  2K  [R0402]  203.42 120.65 180 top
R1267  0  [R0402]  202.66 124.08 0 top
R1268  0  [R0402]  200.88 127.25 0 top
R1269  2K  [R0402]  200.88 126.19 180 top
R1270  2K  [R0402]  202.66 125.09 180 top
R1271  100  [R0402]  196.41 184.86 0 top
R1272  0  [R0402]  198.21 125.98 0 top
R1273  75  [R0402]  26.39 156.19 180 top
R1274  75  [R0402]  26.39 157.33 180 top
R1275  75  [R0402]  26.09 163.56 180 top
R1276  75  [R0402]  26.09 164.7 180 top
R1277  75  [R0402]  199.8 163.02 0 top
R1278  75  [R0402]  199.8 164.04 0 top
R1279  75  [R0402]  199.8 165.06 0 top
R1280  75  [R0402]  199.8 166.07 0 top
R1281  33  [R0402]  44.05 170.4 180 top
R1282  4.7K  [R0402]  139.63 155.85 0 top
R1283  4.7K  [R0402]  124.35 160.18 90 top
R1284  4.7K  [R0402]  144.92 156.31 0 top
R1285  0  [R0402]  199.61 120.65 0 top
R1286  0  [R0402]  198.16 128.03 0 top
R1287  0  [R0402]  200.25 125.09 0 top
R1288  10K  [R0402]  133.44 52.96 270 bottom
R1289  10K  [R0402]  128.62 51.94 90 bottom
R1290  10K  [R0402]  198.16 127.03 0 top
R1291  1.2K  [R0402]  131.16 35.94 90 bottom
R1292  100  [R0402]  195.27 188.42 270 top
R1293  100  [R0402]  194.25 188.42 270 top
R1294  100  [R0402]  192.22 188.42 270 top
R1295  100  [R0402]  193.24 188.42 270 top
R1296  100  [R0402]  196.28 188.42 270 top
R1297  1K  [R0402]  17.52 167.37 180 top
R1298  4.7K  [R0402]  19.21 154.14 270 top
R1299  4.7K  [R0402]  20.23 154.14 270 top
R1300  1K  [R0402]  18.77 151.33 180 top
R1301  4.7K  [R0402]  19.69 138.62 270 top
R1302  4.7K  [R0402]  20.7 138.62 270 top
R1303  1K  [R0402]  179.59 174.37 90 top
R1304  4.7K  [R0402]  167.96 176.08 90 top
R1305  4.7K  [R0402]  166.2 175.36 90 top
R1306  1K  [R0402]  168.16 177.14 0 bottom
R1307  4.7K  [R0402]  177.04 184.07 0 bottom
R1308  4.7K  [R0402]  177.29 185.08 0 bottom
R1309  4.7K  [R0402]  145.63 163.88 0 bottom
R1310  10K  [R0402]  16.76 155.79 270 top
R1311  10K  [R0402]  18.67 138.63 270 top
R1312  100  [R0402]  196.79 177.5 180 top
R1313  100  [R0402]  196.79 175.46 180 top
R1314  100  [R0402]  196.79 176.48 180 top
R1315  100  [R0402]  196.77 174.42 180 top
R1316  100  [R0402]  196.79 178.51 180 top
R1317  100  [R0402]  196.41 182.83 0 top
R1318  100  [R0402]  196.41 179.78 0 top
R1319  100  [R0402]  196.41 183.85 0 top
R1320  100  [R0402]  196.41 181.81 0 top
R1321  100  [R0402]  196.41 180.8 0 top
R1322  10K  [R0402]  145.48 46.96 270 bottom
R1323  10K  [R0402]  142.13 50.85 90 top
R1324  0  [R0402]  144.47 46.96 270 bottom
R1325  10K  [R0402]  142.92 46.38 180 bottom
R1326  2K  [R0402]  144.57 54.13 270 top
R1327  0  [R0402]  140.56 59.44 90 bottom
R1328  2K  [R0402]  139.54 59.44 270 bottom
R1329  4.7K  [R0402]  144.45 43.71 90 bottom
R1330  4.7K  [R0402]  141.57 59.44 270 bottom
R1331  100  [R0402]  44.67 187.73 0 bottom
R1332  100  [R0402]  44.67 188.77 180 bottom
R1333  100  [R0402]  176.62 188.09 90 bottom
R1334  100  [R0402]  175.48 188.09 270 top
S1  STS-02  [SW_STS-02]  176.16 136.06 180 top
S3  STS-02  [SW_STS-02]  166.67 129.31 0 top
TP1  TP  [TP30]  54.15 163.53 270 bottom
TP2  TP  [TP30]  52.72 162.32 270 bottom
TP3  TP  [TP30]  175.46 144.51 90 bottom
TP4  TP  [TP30]  178.18 145.21 90 bottom
TP5  TP  [TP30]  87.3 139.39 180 bottom
TP6  TP  [TP30]  88.45 141.29 180 bottom
TP7  TP  [TP30]  84.21 139.19 180 bottom
TP8  TP  [TP30]  81.77 142.88 180 bottom
TP9  TP  [TP30]  177.45 199.04 180 bottom
TP10  TP  [TP30]  172.44 198.84 180 bottom
TP11  TP  [TP30]  179.03 198.83 180 bottom
TP12  TP  [TP30]  173.49 196.1 180 bottom
TP172  TP  [TP26D10]  106.29 122.32 270 top
TP173  TP  [TP26D10]  105.89 117.96 270 top
TP174  TP  [TP26D10]  95.88 124.54 270 top
TP175  TP  [TP26D10]  94.07 118.65 270 top
U1  9VRS4339BKLFT  [QFN56_THXL]  144.99 117.51 90 top
U2  Processor  [BGA1283]  70.03 75.8 0 top
U3  BAT54C  [SOT23_123]  132.88 70.43 0 top
U4  W25Q64FVSSIG  [SOIC8_5-3XA]  102.1 100.49 0 top
U5  SOCKET8P  [SOCKET8S]  102.1 100.48 180 top
U9  EMC1428-7-AP-TR  [QFN16_THXJ]  63.94 98.93 180 top
U10  ISL90728  [SC70-6]  20.76 4.27 0 top
U11  LMV321AS5X  [SOT23-5XA]  23.08 8.35 0 top
U13  M24C04-WMN6TP  [SOIC8]  156.71 154.61 270 top
U14  AST1300A1-GP  [BGA408]  77.77 134.86 270 top
U15  K4B1G1646E-HCF8  [BGA96XA]  55.27 134.96 0 top
U16  SN74LVC1G07DCKR  [SC70-5]  57.16 123.22 90 top
U30  88SE9130B1-NAA2C000  [QFN76_THXA]  153.56 59.92 90 top
U31  W25X40BVSSIG  [SOIC8_5-3XA]  141.13 65.55 90 top
U32  UPD720201K8-701-BAC-A  [QFN68_THXB]  179.28 100.94 0 top
U33  MX25L5121EMC20G  [SOIC8]  170.54 88.22 270 top
U35  WG82574L S LBA9 A1  [QFN64_THXD]  56.6 154.92 90 top
U36  M95320-WMN6TP  [SOIC8]  70.9 155.71 0 top
U37  WG82574L S LBA9 A1  [QFN64_THXD]  173.05 153.1 270 top
U38  M95320-WMN6TP  [SOIC8]  172.19 165.75 270 top
U43  IT8783F-L  [QFP128]  146.04 38.64 270 top
U44  BAT54S-7-F  [SOT23_123]  33.96 56.83 90 top
U45  BAT54S-7-F  [SOT23_123]  32.95 49.72 90 top
U46  BAT54S-7-F  [SOT23_123]  32.51 41.55 90 top
U47  BAT54S-7-F  [SOT23_123]  32.95 46.22 90 top
U48  BAT54S-7-F  [SOT23_123]  33.95 53.3 90 top
U49  BAT54S-7-F  [SOT23_123]  30.01 66.85 180 top
U50  BAT54S-7-F  [SOT23_123]  29.83 59.42 90 top
U51  MAX3243CPWR  [TSSOP28]  167.38 33.46 90 top
U52  MAX3243CPWR  [TSSOP28]  24.25 23.12 180 top
U53  IP4220CZ6  [SOT457]  186.67 41.49 180 top
U54  IP4220CZ6  [SOT457]  186.68 61.51 180 top
U55  MAX3243CPWR  [TSSOP28]  18.87 161.14 180 top
U56  MAX3243CPWR  [TSSOP28]  19.5 145.47 180 top
U57  MAX3243CPWR  [TSSOP28]  174.33 175.83 90 top
U58  74LVC1G17GV  [SC74AXA]  168.02 136.72 270 top
U59  MAX3243CPWR  [TSSOP28]  174.33 175.83 90 bottom
U60  PCA9516APW  [TSSOP16]  129.72 170.35 270 top
U61  SC18IM700IPW  [TSSOP16]  129.72 164.63 270 top
U62  PCA9535CPW  [TSSOP24]  96.85 173.39 90 bottom
U63  PCA9535CPW  [TSSOP24]  67.26 176.32 270 bottom
U64  PCA9535CPW  [TSSOP24]  128.48 177.2 90 bottom
U65  PCA9535CPW  [TSSOP24]  112.47 176.57 90 bottom
U66  PCA9535CPW  [TSSOP24]  160.1 173.52 90 bottom
U67  M24C64  [SOIC8]  112.49 177.46 270 top
U68  TMP05ARTZ-500RL7  [SOT23-5]  120.86 166.79 0 top
U69  ADT7470ARQZ  [QSOP16]  112.5 171.88 270 top
U70  ADT7470ARQZ  [QSOP16]  112.5 166.11 270 top
U71  TMP05ARTZ-500RL7  [SOT23-5]  112.75 166.2 90 bottom
U73  SC18IM700IPW  [TSSOP16]  96.86 165.98 270 bottom
U84  74LVC1G17GV  [SC74AXA]  77.5 173.53 180 top
U85  74LVC1G17GV  [SC74AXA]  63.78 173.53 180 top
U86  74LVC1G17GV  [SC74AXA]  70.64 173.53 180 top
U87  74LVC1G17GV  [SC74AXA]  60.22 173.53 180 top
U88  74LVC1G17GV  [SC74AXA]  74.07 173.53 180 top
U89  74LVC1G17GV  [SC74AXA]  67.18 173.53 180 top
U92  2N7002LT1G  [SOT23_GDS]  56.53 173.72 0 top
U93  2N7002LT1G  [SOT23_GDS]  56.66 182.9 180 top
U94  2N7002LT1G  [SOT23_GDS]  77.8 178.8 180 top
U95  2N7002LT1G  [SOT23_GDS]  70.44 178.8 180 top
U96  2N7002LT1G  [SOT23_GDS]  63.2 178.8 180 top
U97  2N7002LT1G  [SOT23_GDS]  74.12 178.8 180 top
U98  2N7002LT1G  [SOT23_GDS]  66.75 178.8 180 top
U99  2N7002LT1G  [SOT23_GDS]  59.64 178.8 180 top
U100  ADM1178-2ARMZ-R7  [MSOP10]  45.67 179.99 180 top
U101  MAX809SEUR+  [SOT23_123]  200.4 114.51 270 top
U102  EPM240F100C5N  [BGA100]  188.54 120.87 180 top
U103  2N7002LT1G  [SOT23_GDS]  135.73 54.47 270 top
U104  2N7002LT1G  [SOT23_GDS]  102.79 160.94 180 top
U105  2N7002LT1G  [SOT23_GDS]  107.85 161.14 0 top
U106  74LVC1G17GV  [SC74AXA]  186.71 138 90 top
U107  2N7002LT1G  [SOT23_GDS]  124.84 156.33 180 top
U108  2N7002LT1G  [SOT23_GDS]  121.33 156.33 180 top
U109  2N7002LT1G  [SOT23_GDS]  47.05 170.55 270 top
U110  2N7002LT1G  [SOT23_GDS]  128.35 156.33 180 top
U111  2N7002LT1G  [SOT23_GDS]  130.18 152.31 180 top
U114  2N7002LT1G  [SOT23_GDS]  56.49 169.63 270 top
U115  LC4032-75T48C  [TQFP48]  100.15 120.89 270 top
U116  FDV301N  [SOT23_GDS]  138.6 158.61 180 top
U117  FDV301N  [SOT23_GDS]  134.88 154.54 180 top
U118  FDV301N  [SOT23_GDS]  134.93 158.61 180 top
U119  RT9059GQW  [DFN10_THXE]  108.37 136.24 0 top
U120  RT9059GQW  [DFN10_THXE]  45.37 102.21 270 top
U121  RT9059GQW  [DFN10_THXE]  43.67 128.35 0 top
U122  RT9059GQW  [DFN10_THXE]  94.96 139.75 180 top
U123  TPS51200  [DFN10_THXB]  127.42 22.31 180 top
U124  FDMS3664S  [POWER56XA]  121.13 125.19 90 top
U125  PI7C9X20303SLFDE  [LQFP128XB]  145.57 143.58 90 top
U126  FDV301N  [SOT23_GDS]  121.32 160.4 90 top
U127  FDV301N  [SOT23_GDS]  145.71 158.8 0 top
U128  EPM240T100C5N  [TQFP100_H56]  92.03 172.12 270 top
U129  EPM240T100C5N  [TQFP100_H56]  149.56 171.11 270 top
U130  RT9059GQW  [DFN10_THXE]  173.67 78.36 90 top
U131  74LVC2G14GW  [SOT363]  112.51 181.32 270 top
U132  74HC2G125DP  [TSSOP8_3XA]  37.14 51.86 90 top
U133  SN74LVC1G07DCKR  [SC70-5]  113.68 169.45 270 bottom
U134  M24C02-WMN6TP  [SOIC8]  35.77 100.07 180 top
U135  SN74LVC1G125DCKR  [SC70-5]  139.68 56.42 270 top
U136  SN74LVC1G125DCKR  [SC70-5]  139.66 53.93 270 top
U137  NA0069R LF  [TRF24_NA0069RLF]  33.9 160.38 180 top
U138  NA0069R LF  [TRF24_NA0069RLF]  190.06 163.52 90 top
U139  FDV301N  [SOT23_GDS]  142.14 158.64 180 top
U140  2N7002LT1G  [SOT23_GDS]  145.33 161.04 180 bottom
U141  2N7002LT1G  [SOT23_GDS]  173.81 167.14 0 bottom
U142  2N7002LT1G  [SOT23_GDS]  170.33 166.72 180 bottom
U143  2N7002LT1G  [SOT23_GDS]  139.64 160.84 0 bottom
U144  2N7002LT1G  [SOT23_GDS]  15.54 152.8 180 top
U145  SN74LVC1G07DCKR  [SC70-5]  145.99 55.6 90 bottom
U146  SN74LVC1G07DCKR  [SC70-5]  140.94 55.24 180 bottom
Y1  25MHZ  [X_7MXA]  141.28 108.28 180 top
Y2  32.768KHZ  [X_2S_FC145]  96.48 84.69 0 top
Y3  24MHZ  [X_E5FA]  179.4 91.33 90 top
Y4  25MHZ  [X_7A]  55.58 165.97 0 top
Y5  25MHZ  [X_7A]  174.07 142.05 180 top

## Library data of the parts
BT1 = BATTERY
BT1_BATTERY1 H10_NUT H10_SRW PCB TP172-TP175 = TP: alternate symbols: (TOP:TP26D10;BOTTOM:TP30D10)
C1 C5 C9 C69 C72 C73 C76 C77 C79 C80 C91-C95 C124 C126 C130 C172 C173 C176 C199 C224 C225 C228 C275 C286 C360 C367 C376 C382 C393 C413 C424 C430 C431 C439 C445 C473 C474 C483 C771 C782 C783 C810 C812 C813 C818 C820 C821 C828 C830 C831 C836 C838 C854 C857-C859 C885 C908 PC2 PC6 PC7 PC21 PC22 PC66-PC68 PC72-PC74 PC81-PC86 PC91-PC94 PC109 PC110 PC112 PC118 PC119 PC121 PC130-PC133 = CAP_NP: signal model: DEFAULT_CAPACITOR_1e+07pF_2_1
C2-C4 C6-C8 C10-C12 C23 C82 C86-C90 C98-C101 C103 C105-C116 C120 C121 C125 C129 C131 C132 C174 C175 C177 C178 C181 C182 C184-C190 C196 C198 C203-C205 C223 C226 C227 C229-C236 C242-C244 C246-C252 C254-C257 C264-C267 C269 C274 C277 C279 C281-C285 C288 C292 C294-C297 C332 C336-C349 C351-C358 C361 C363-C366 C368-C372 C374 C375 C378-C381 C383 C384 C390-C392 C394-C398 C401-C412 C416-C423 C432-C436 C440-C444 C448-C467 C475 C476 C481 C482 C484 C487 C493 C495 C509 C511-C514 C521-C524 C530-C534 C536-C539 C542-C555 C562-C586 C599 C601 C603 C606 C609 C612 C615-C621 C766-C770 C772-C776 C797 C799 C801 C855 C856 C860-C882 C888-C897 C900-C907 C930-C932 C1119-C1122 PC4 PC5 PC11 PC12 PC20 PC25 PC26 PC29-PC31 PC44 PC75 PC77 PC78 PC89 PC95 PC96 PC98 PC101 PC106 PC111 PC115 PC120 PC122 = CAP_NP: signal model: DEFAULT_CAPACITOR_100000pF_2_1
C13 C14 C141 C590 = CAP_NP: signal model: DEFAULT_CAPACITOR_33pF_2_1
C15-C20 C26-C28 C30 C587 C589 C591-C597 C610 C613 = CAP_NP: signal model: DEFAULT_CAPACITOR_10pF_2_1
C21 C22 C192 C193 = CAP_NP: signal model: CAP_NP_C0402_DISCRETE_0.1UF_0.1UF
C24 C25 = CAP_NP: signal model: DEFAULT_CAPACITOR_18pF_2_1
C29 C31-C33 C35-C40 C45-C47 C49-C51 C54-C57 C59 C64-C68 C70 C71 C74 C75 C78 C84 C85 C96 C97 C117 C122 C123 C127 C128 C253 C263 C276 C278 C287 C293 C359 C377 C485 C486 C491 C496 C510 C520 C784-C793 C798 C802 C809 C817 C827 C835 C839 C845 C847 C849 C853 C883 C886 C887 C934 PC10 PC14 PC15 PC18 PC41 PC76 PC87 PC104 PC105 PC114 = CAP_NP: signal model: DEFAULT_CAPACITOR_1e+06pF_2_1
C34 C41 C43 C44 C52 C53 C58 C280 C488 PC16 PC17 PC27 PC28 PC32-PC39 PC45-PC47 PC49 PC50 PC52-PC61 PC107 PC116 PC117 PC125 PC126 = CAP_NP: signal model: DEFAULT_CAPACITOR_2.2e+07pF_2_1
C42 = CAP_NP: room: VR_P1V05_PCH; signal model: DEFAULT_CAPACITOR_2.2e+07pF_2_1
C48 C119 C373 C414 C415 C446 C447 C556 C559 = CAP_NP: signal model: DEFAULT_CAPACITOR_4.7e+06pF_2_1
C60-C63 C81 C102 C104 PC1 PC3 PC88 = CAP_NP: signal model: DEFAULT_CAPACITOR_2.2e+06pF_2_1
C83 C118 C273 C425-C429 C468-C472 C489 C490 C492 C494 C781 C816 C824 C834 C884 PC69 PC103 PC123 PC124 = CAP_NP: signal model: DEFAULT_CAPACITOR_10000pF_2_1
C134 C135 C146-C148 C151-C153 C157 C161 C170 C171 C777 C778 C795 C811 C819 C826 C829 C837 C840 C842 C846 C848 C850 C852 C909 C933 = CAP_NP: signal model: DEFAULT_CAPACITOR_100000pF_2_1; room: VR_P1V05_PCH
C136 = CAP_NP: room: VR_P1V05_PCH; signal model: DEFAULT_CAPACITOR_10000pF_2_1
C137-C139 = CAP_NP: signal model: DEFAULT_CAPACITOR_180pF_2_1
C140 = CAP_NP: room: VR_P1V05_PCH; signal model: DEFAULT_CAPACITOR_1e+06pF_2_1
C142 = CAP_NP: room: VR_P1V05_PCH; signal model: DEFAULT_CAPACITOR_33pF_2_1
C143 C179 C180 C183 C191 C334 C335 PC102 = CAP_NP: room: VR_P1V05_PCH; signal model: DEFAULT_CAPACITOR_100000pF_2_1
C144 C154 C158 C168 C169 C197 = CAP_NP: signal model: DEFAULT_CAPACITOR_1e+07pF_2_1; room: VR_P1V05_PCH
C145 = CAP_NP: signal model: DEFAULT_CAPACITOR_1e+06pF_2_1; room: VR_P1V05_PCH
C149 C150 = CAP_NP: signal model: DEFAULT_CAPACITOR_27pF_2_1; room: VR_P1V05_PCH
C155 C156 C159 C160 = CAP_NP: signal model: DEFAULT_CAPACITOR_4.7e+06pF_2_1; room: VR_P1V05_PCH
C162-C167 = CAP_NP: signal model: DEFAULT_CAPACITOR_10000pF_2_1; room: VR_P1V05_PCH
C194 = CAP_NP: room: VR_P1V05_PCH
C200 C598 = CAP_NP
C202 C399 C400 C437 C438 = CAP_NP: signal model: DEFAULT_CAPACITOR_27pF_2_1
